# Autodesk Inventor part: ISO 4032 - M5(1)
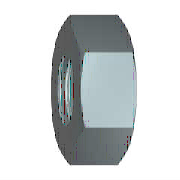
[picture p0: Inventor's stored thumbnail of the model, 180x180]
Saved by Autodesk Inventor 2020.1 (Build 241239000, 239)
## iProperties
Created: 2019-01
Part Number: ISO 4032 - M5(1)
Material: Edelstahl, 440C
Description: Sechskantmutter
Document SubType Name: Modeling
Standard: ISO 4032
Designer: lutzd
Standards Organization: DIN
Language: de-DE
Size Designation: M5
Categories: <MemberInstance><Categories><Category DisplayName="Verbindungselemente" InternalName="e4da775c-781d-43d5-af7c-5136215cf5a6" Mnemonic="FSTN"><Category DisplayNam
Mass: 1.45184 g
Surface Area: 2.51913 cm^2
Volume: 0.187334 cm^3
Density: 7.75 g/cm^3
Appearance: Halbpoliert
IsCustomPart: 0
Author: lutzd
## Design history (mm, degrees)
workaxis "Work Axis1"
workplane "Work Plane1"
sketch "Skizze1"
  geometry: L1 (-4.619, 0)-(-2.309, 4); L2 (-2.309, 4)-(2.309, 4); L3 (2.309, 4)-(4.619, 0); L4 (4.619, 0)-(2.309, -4); L5 (2.309, -4)-(-2.309, -4); L6 (-2.309, -4)-(-4.619, 0); 2 further points
  constraints: 12 end point, 1 coincident, 1 horizontal, 11 other
  dimensions: "d0" = 9.2376 distance of L3.end L1.start (= 1.1547 x SW)
extrude "Körper" new body sketch "Skizze1" distance "d1" = 4.7 (= KOH); taper "d2" = 0 deg
sketch "Skizze2"
  geometry: L1 (0, 2.309)-(0, 4.619) reference; L2 (0, 4.619)-(4.7, 4.619) reference; L3 (4.7, 2.309)-(4.7, 4.619) reference; L4 (-0.94, 0)-(5.64, 0) reference; L5 (0.675, 4.619)-(0, 3.45); L6 (4.025, 4.619)-(4.7, 3.45)
  constraints: 4 end point, 4 point on line
  dimensions: "d3" = 30 deg angle of L1 L5 (= ANG1); "d4" = 30 deg angle of L3 L6 (= ANG2); "d5" = 6.9 diameter of L5.end L4 (= SW0); "d6" = 6.9 diameter of L6.end L4 (= SW01)
revolve "Fase1" stored, may be unused: angle "d7" = 90 deg
sketch "Skizze3"
  geometry: 4 further points
  constraints: 1 coincident, 1 other
hole "Gewinde" sketch "Skizze3" diameter "d25" = 4.134; stored, may be unused: countersink angle "d29" = 82 deg, drill point angle "d31" = 118 deg; dims "d26" = 6, "d27" = 4, "d28" = 2, "d30" = 8
body "Solid1"
chamfer "Fase2" distance "d8" = 0.43301 (= -0.5 x GD1 + 0.5 x NND); stored, may be unused: angle "d9" = 30 deg, second distance "d40" = 0.43301 (= -0.5 x GD1 + 0.5 x NND)
chamfer "Fase3" distance "d10" = 0.43301 (= -0.5 x GD1 + 0.5 x NND); stored, may be unused: angle "d11" = 30 deg, second distance "d41" = 0.43301 (= -0.5 x GD1 + 0.5 x NND)
other parameters: "ANG1" = 30 deg [user parameter; used in 1 equation term], "ANG2" = 30 deg [user parameter; used in 1 equation term], "NND" = 5 [user parameter; used in 4 equation terms], "KOH" = 4.7 [user parameter; used in 1 equation term], "SW" = 8 [user parameter; used in 2 equation terms], "SW0" = 6.9 [user parameter; used in 1 equation term], "SW01" = 6.9 [user parameter; used in 1 equation term], "GD1" = 4.13397 (computed from THREADDIA, PTC, TOA) [user parameter; used in 4 equation terms], "d13" = 0, "d14" = 0, "d39" = 0, "d42" = 0, "GUL" = 0.43301 (= 0.541266 x PTC) [user parameter], "TPU" = 12.5 (computed from PTC) [user parameter], "THREADDIA" = 5 [user parameter; used in 1 equation term], "TOA" = 30 deg [user parameter; used in 1 equation term], "PTC" = 0.8 [user parameter; used in 4 equation terms], "E0" = 9.24 (= 1.155 x SW) [user parameter], "GAL" = 0.43301 (= 0.541266 x PTC) [user parameter]
